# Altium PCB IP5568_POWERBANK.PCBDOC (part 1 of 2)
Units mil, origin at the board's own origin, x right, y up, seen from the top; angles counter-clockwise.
Board outline 4566.93 x 4566.93 mil, 4 copper layers (Top Layer, MID1, MID2, Bottom Layer), stack 38.627 mil thick; 85 components, 61 nets, 294 pads, 184 vias.
Unrouted connection lines stored in the file: 1.
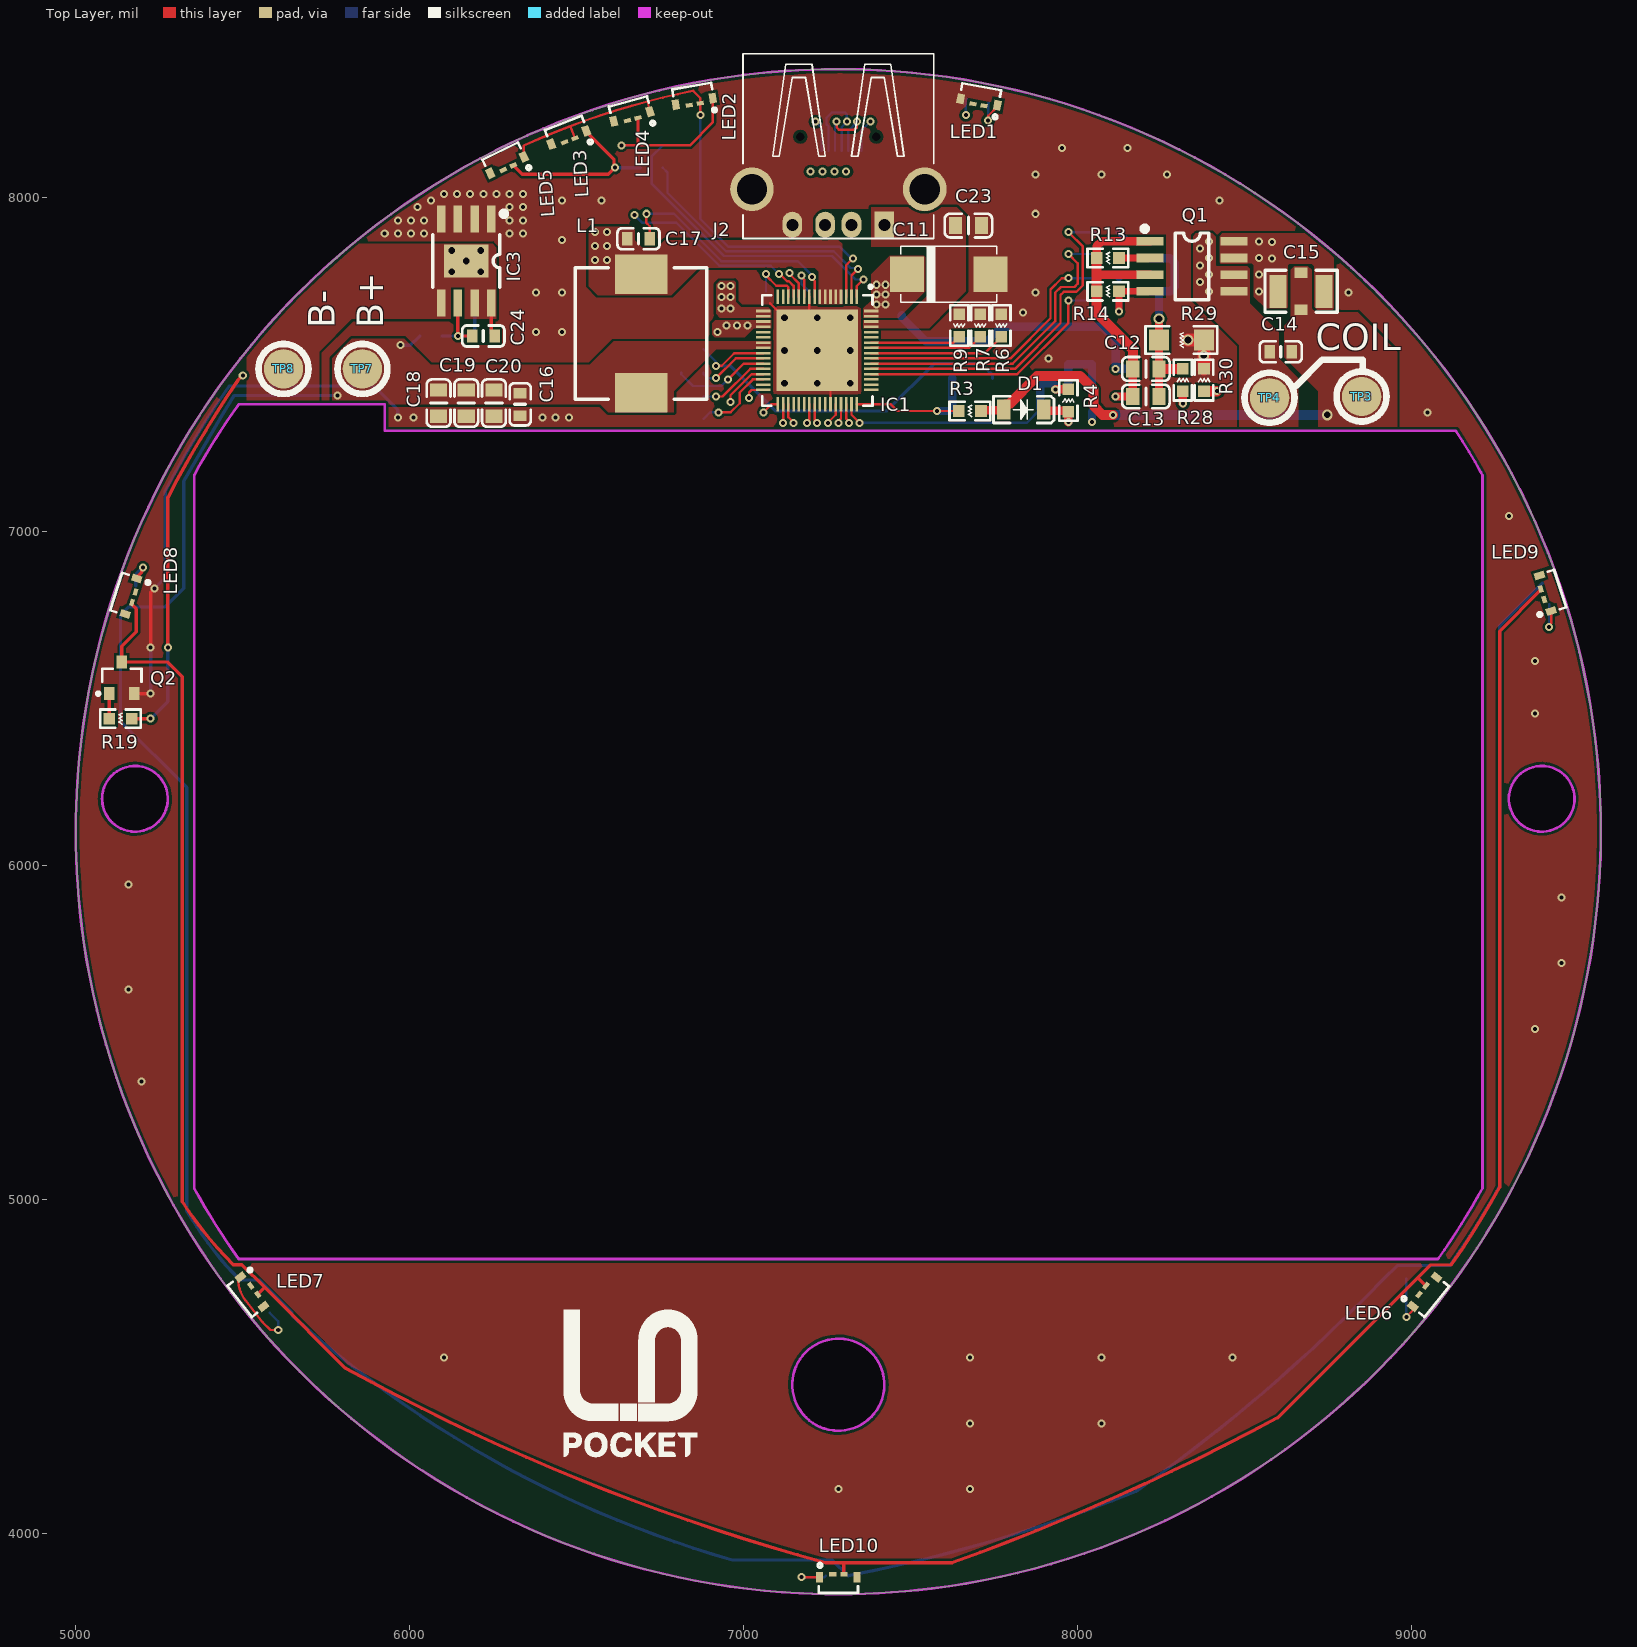
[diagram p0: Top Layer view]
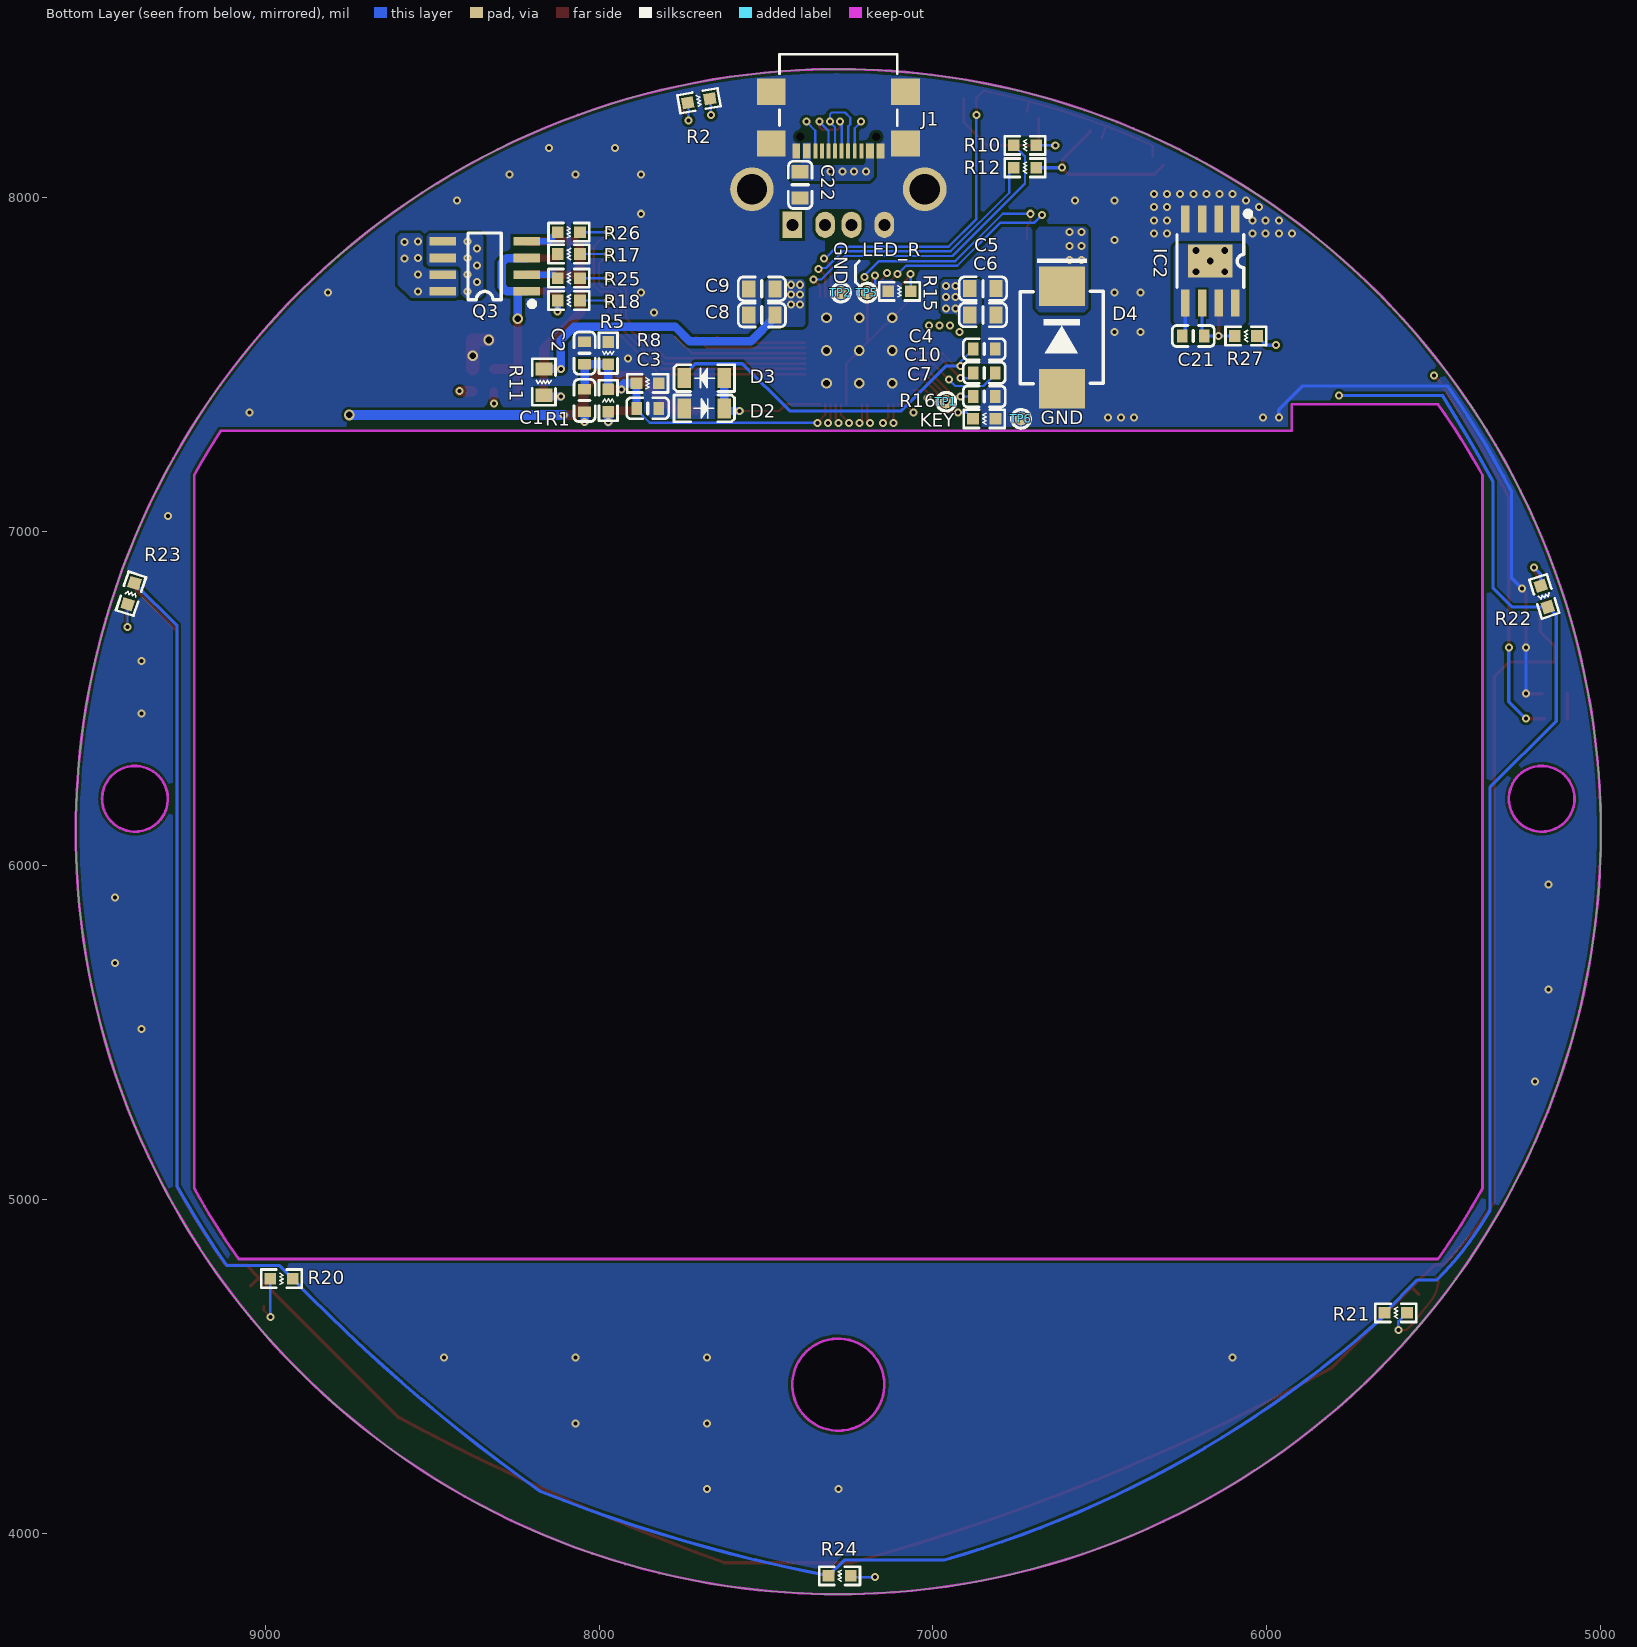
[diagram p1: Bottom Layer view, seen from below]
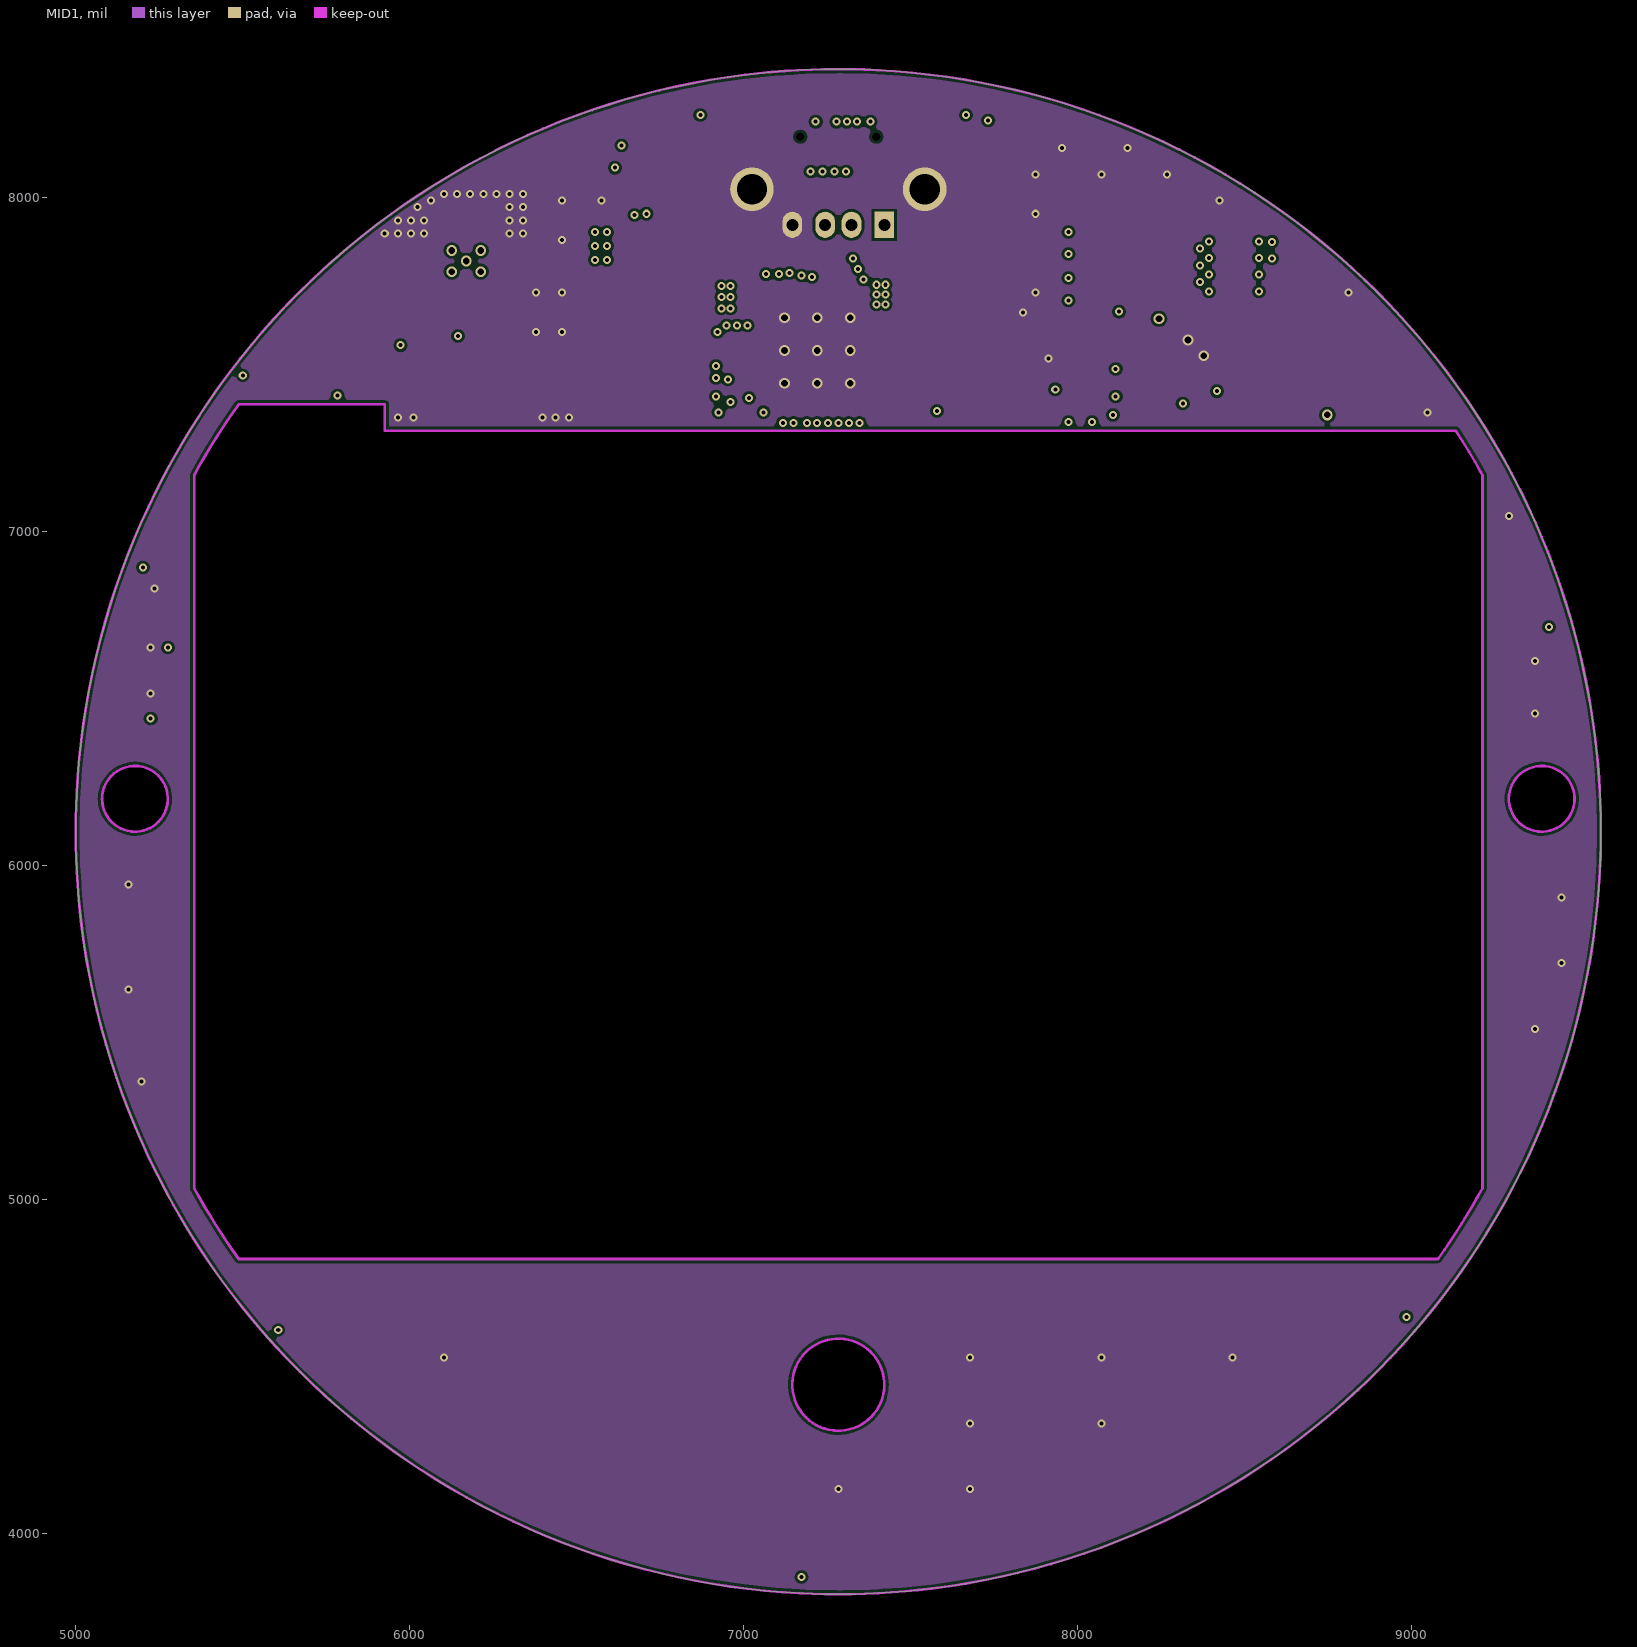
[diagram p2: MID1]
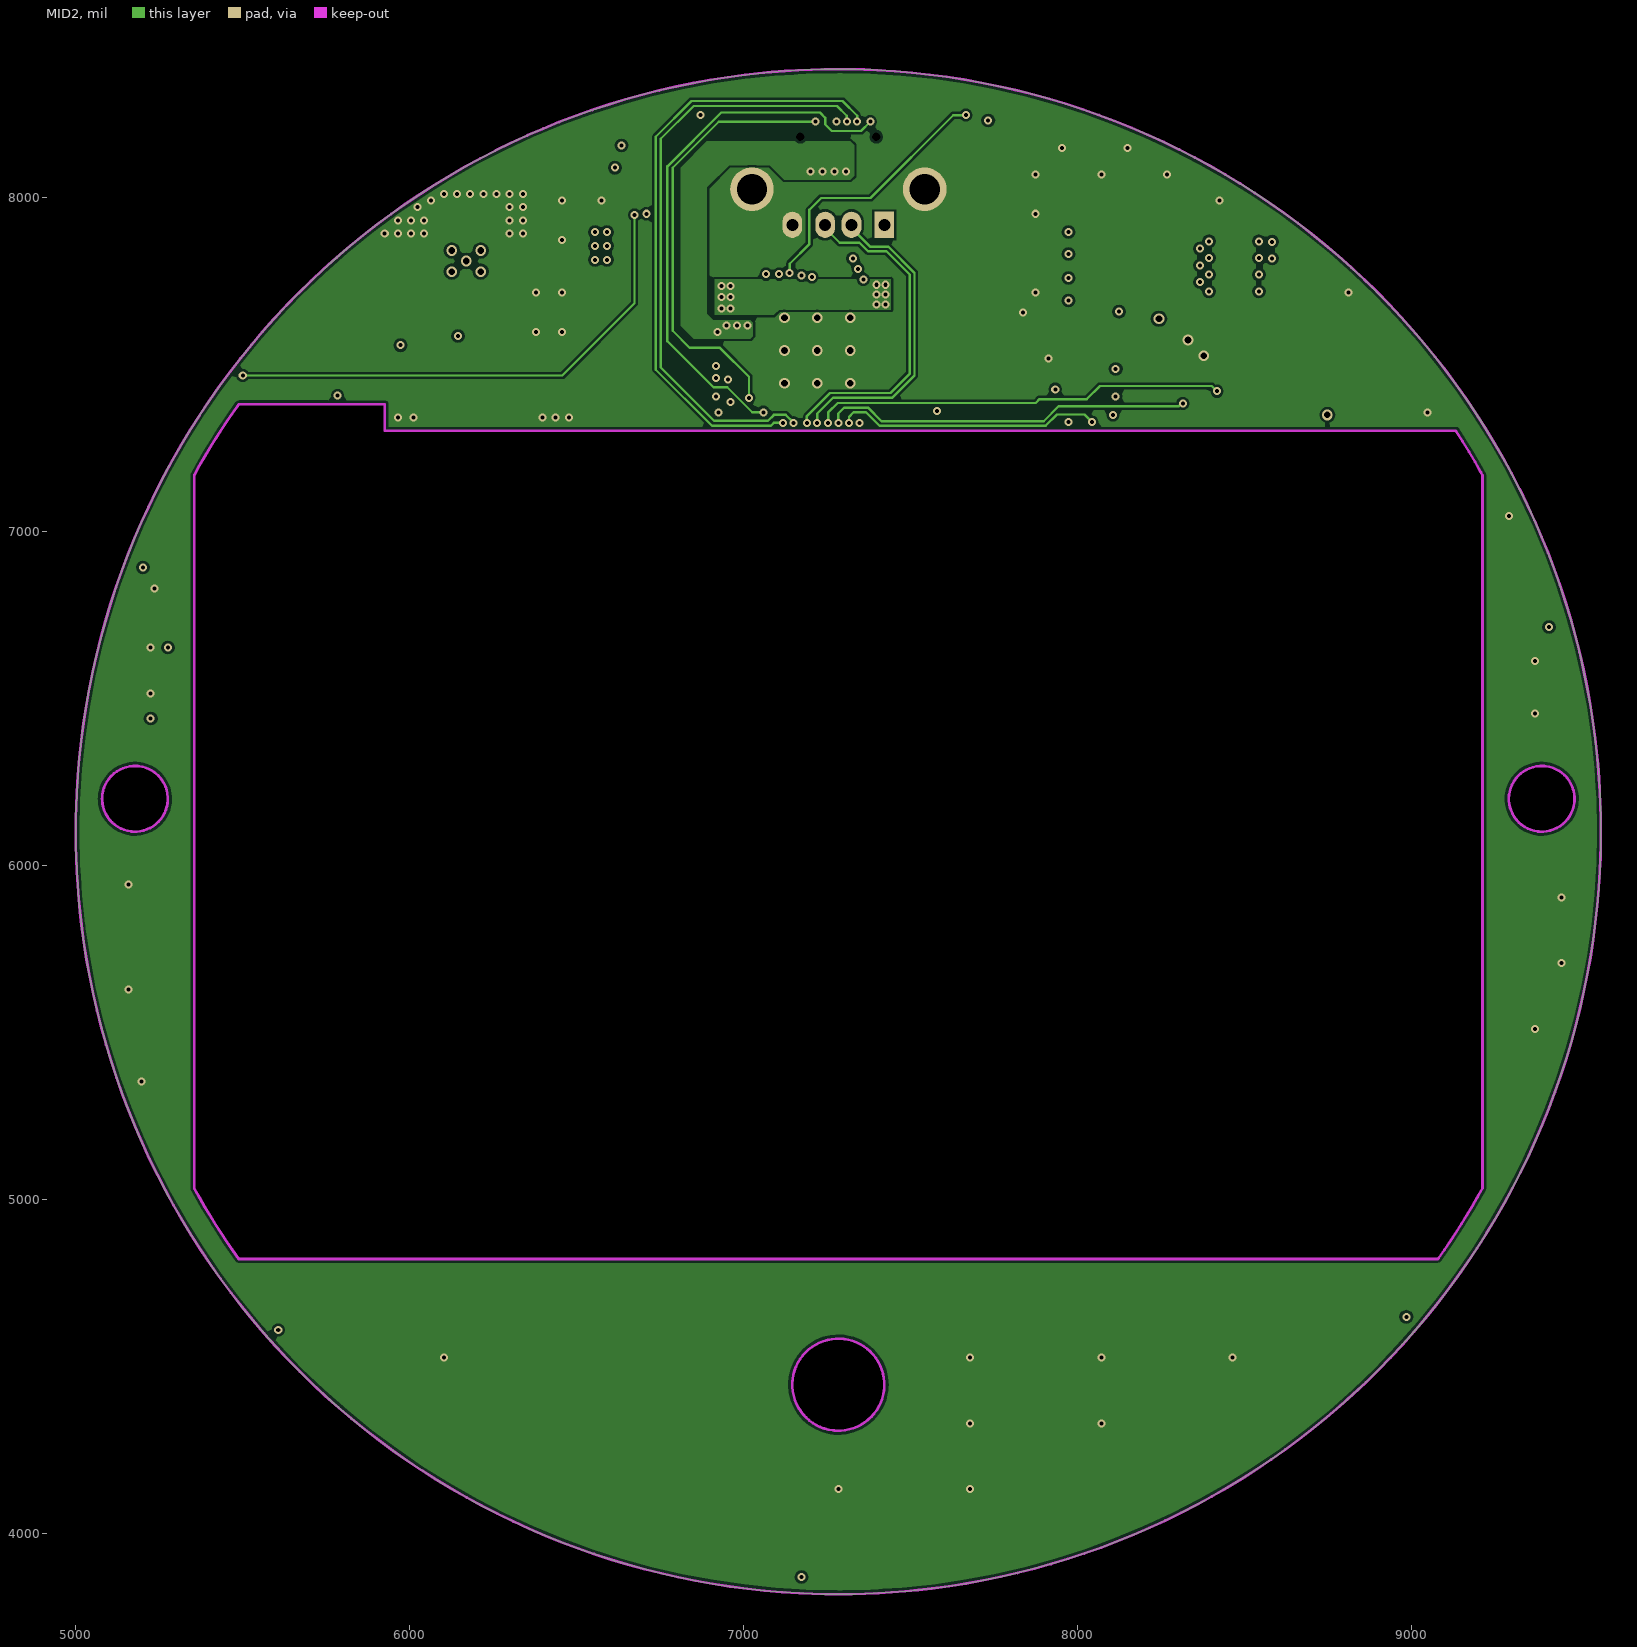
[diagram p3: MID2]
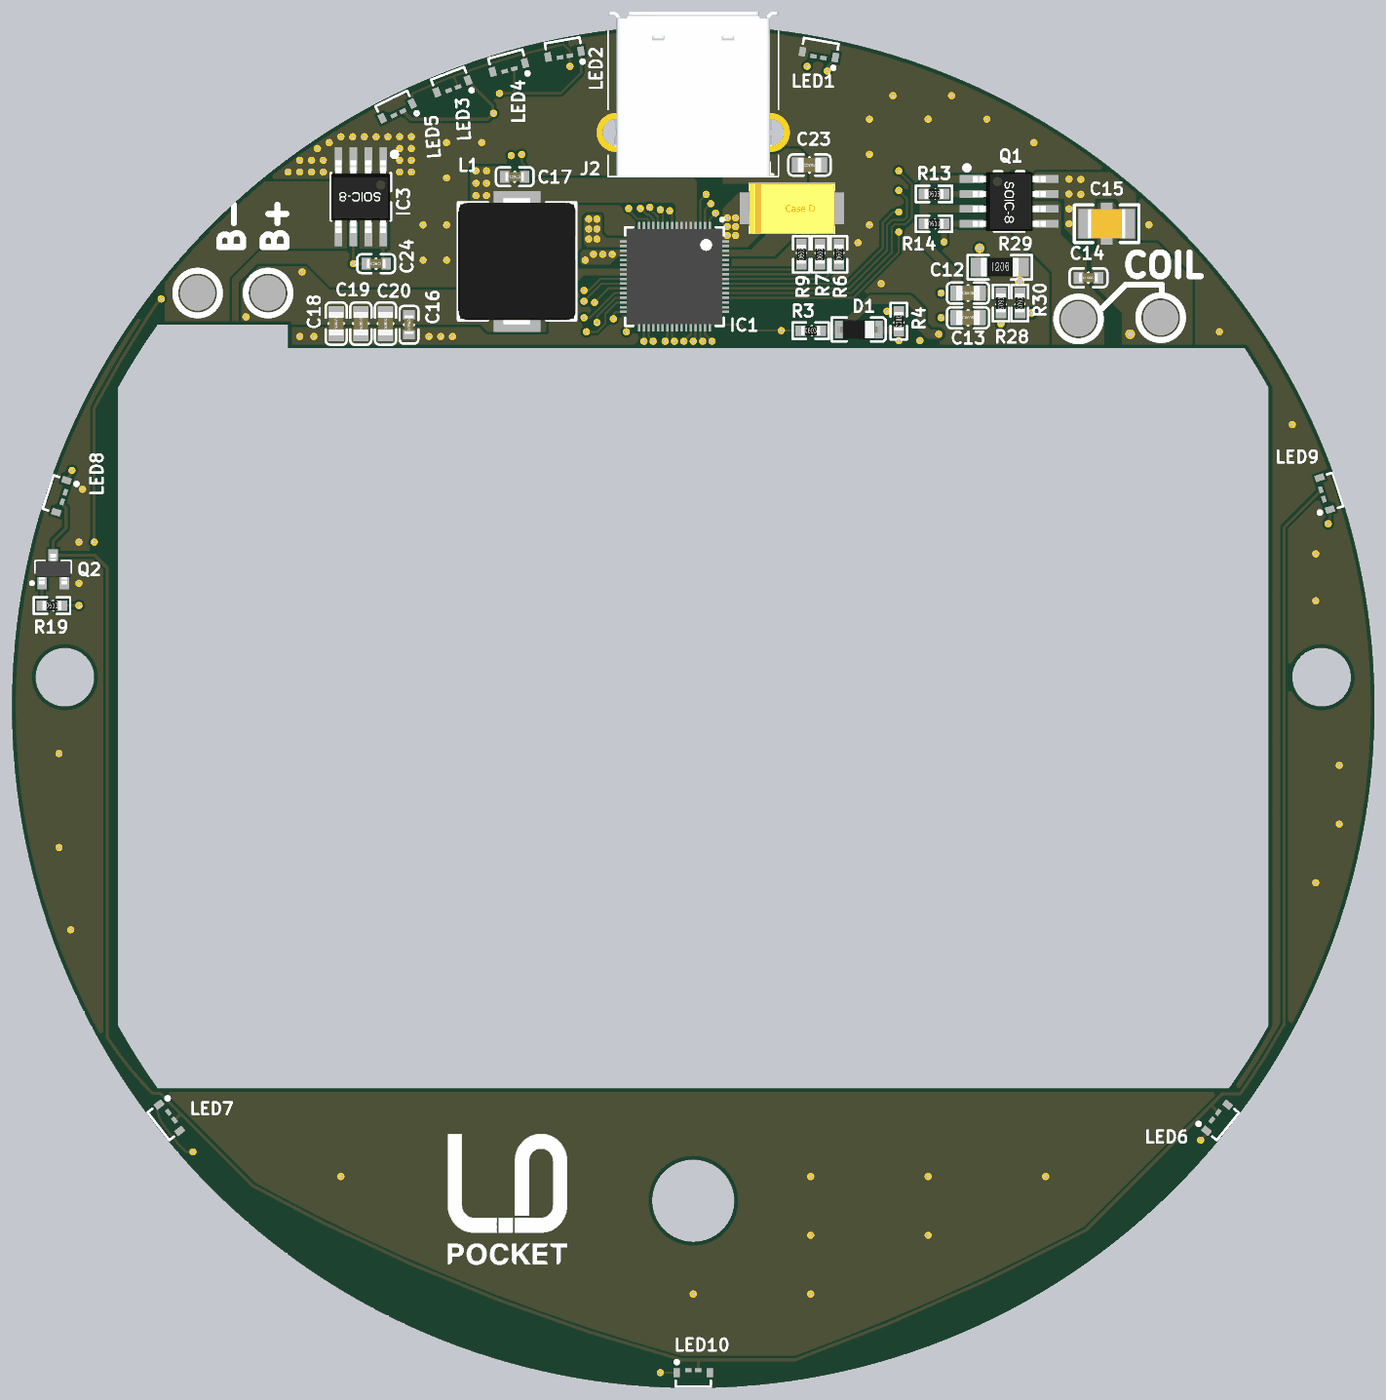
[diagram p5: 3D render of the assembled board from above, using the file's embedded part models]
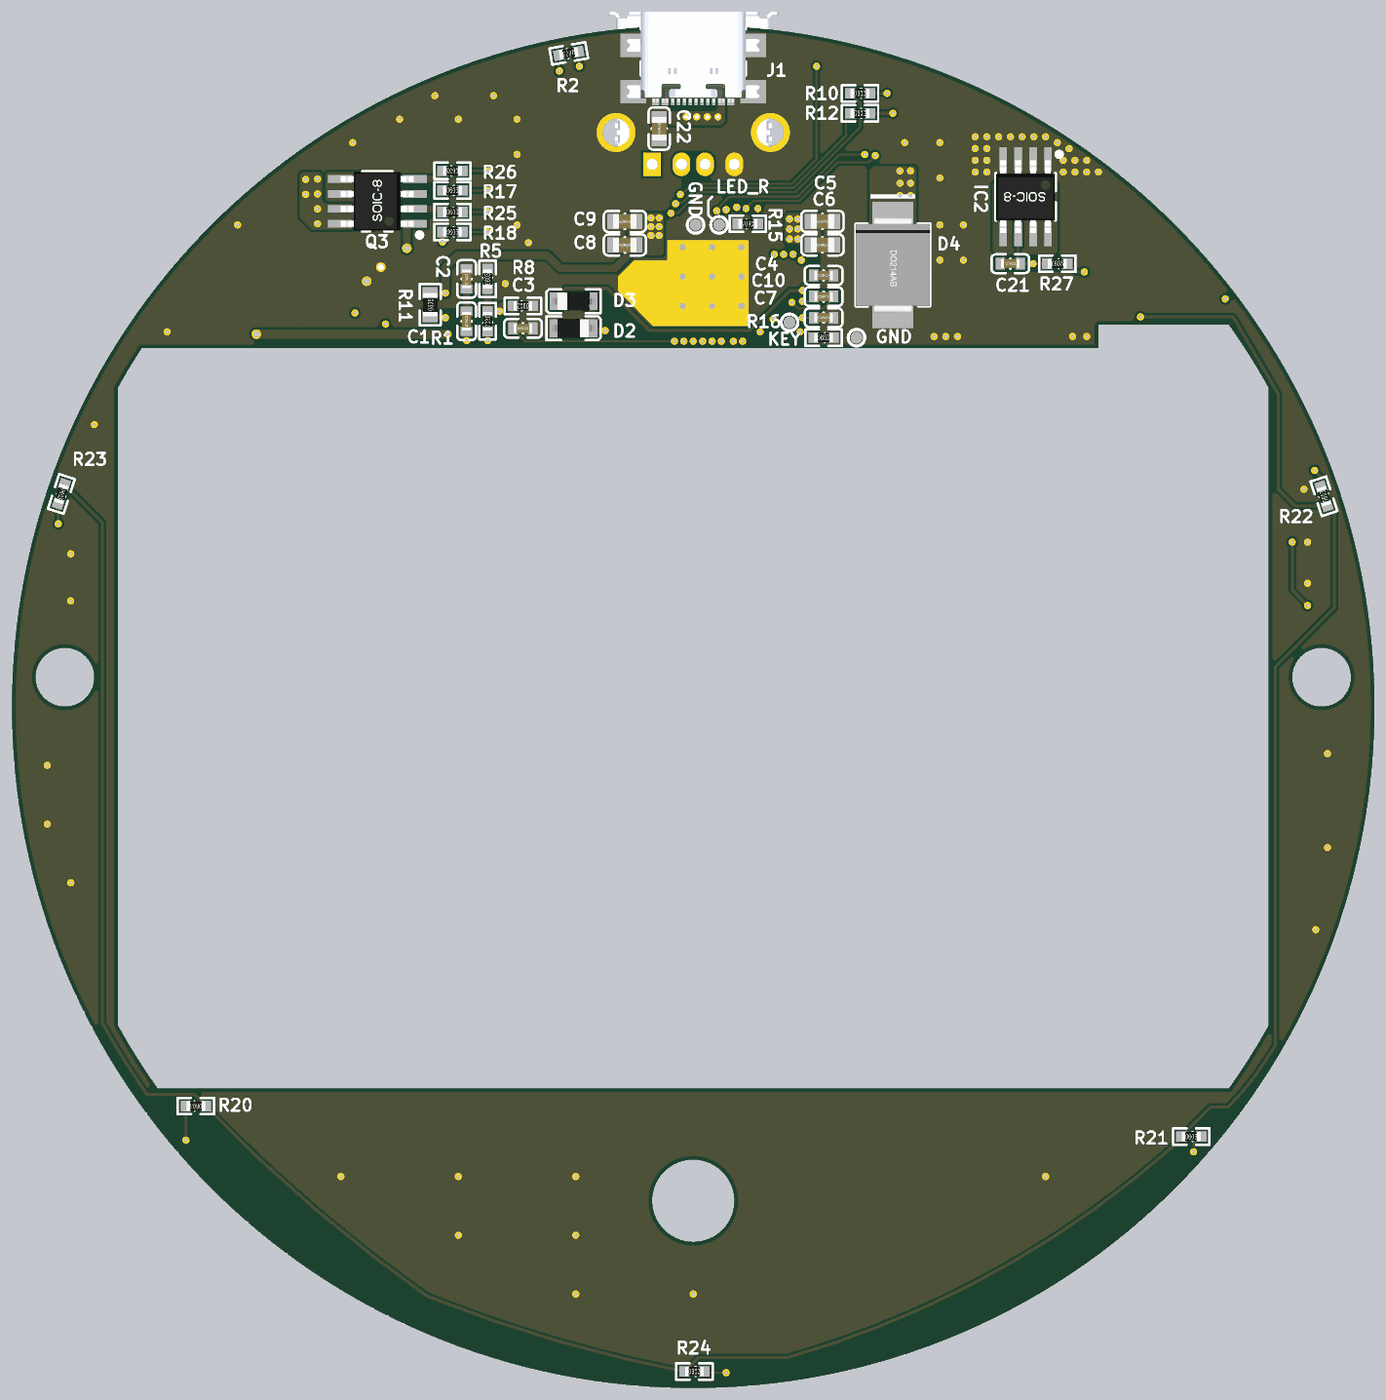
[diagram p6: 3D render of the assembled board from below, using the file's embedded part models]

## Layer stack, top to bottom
Top Solder: solder mask 0.4, Solder Resist, Dk 3.5
Top Layer: signal copper 1.4
Dielectric 1: prepreg 11.0236, PP-006, Dk 4.1
MID1: signal copper 1.378
Dielectric 2: prepreg 11.0236, PP-006, Dk 4.1
MID2: signal copper 1.378
Dielectric1: dielectric 11.0236, FR-4, Dk 4.8
Bottom Layer: signal copper 1.4
Bottom Solder: solder mask 0.4, Solder Resist, Dk 3.5

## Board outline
5000,6102.36 ccw(c7283.46,6102.36) 7283.46,3818.9 ccw(c7283.46,6102.36) 9566.93,6102.36 ccw(c7283.46,6102.36) 7283.46,8385.83 ccw(c7283.46,6102.36)
cut-out: 5418.56,4926.02 cw(c7293.45,6109.41) 5386.41,4978.57 5386.4,4978.57 cw(c7312.75,6120.85) 5355.55,5032.28 5354.33,5034.48 5354.33,7170.25 cw(c7312.02,6084.31) 5386.28,7225.94 cw(c7292.84,6095.68) 5419.37,7279.98 cw(c7274.23,6107.44) 5453.81,7332.77 cw(c7256.69,6119.24) 5487.83,7381.85 5487.91,7381.89 5925.31,7381.89 5925.31,7303.15 9132.65,7303.15 cw(c7294.52,6107.16) 9171.92,7240.51 cw(c7275.49,6095.67) 9207.76,7178.93 9212.6,7170.25 9212.6,5034.48 cw(c7252.63,6121.8) 9181.67,4980.5 cw(c7271.84,6110.43) 9149.55,4927.9 cw(c7290.5,6098.69) 9116.03,4876.28 cw(c7308.61,6086.55) 9080.81,4825.28 9079.07,4822.84 5487.92,4822.84 5487.82,4822.89 cw(c7256.34,6085.25) 5452.27,4874.25 cw(c7274.65,6097.54)
cut-out: 9291.46,6195.76 ccw(c9389.79,6200.8) 9377.72,6103.09 ccw(c9389.7,6201.36) 9384.58,6102.5 ccw(c9389.76,6202.39) 9389.76,6102.36 ccw(c9389.77,6202.41) 9394.79,6102.49 ccw(c9389.75,6200.81) 9487.46,6188.75 ccw(c9389.19,6200.73) 9488.06,6195.6 ccw(c9388.16,6200.78) 9488.19,6200.79 ccw(c9388.15,6200.79) 9488.06,6205.81 ccw(c9389.74,6200.77) 9401.81,6298.48 ccw(c9389.82,6200.22) 9394.95,6299.08 ccw(c9389.77,6199.18) 9389.76,6299.21 ccw(c9389.76,6199.17) 9384.74,6299.09 ccw(c9389.78,6200.76) 9292.07,6212.83 ccw(c9390.33,6200.85) 9291.47,6205.97 ccw(c9391.37,6200.79) 9291.34,6200.79 ccw(c9391.39,6200.78)
cut-out: 7145.85,4439.3 ccw(c7283.5,4446.35) 7266.61,4309.56 ccw(c7283.39,4447.14) 7276.21,4308.73 ccw(c7283.46,4448.59) 7283.47,4308.54 ccw(c7283.48,4448.6) 7290.51,4308.72 ccw(c7283.45,4446.36) 7420.24,4429.47 ccw(c7282.67,4446.25) 7421.08,4439.07 ccw(c7281.22,4446.33) 7421.27,4446.33 ccw(c7281.2,4446.34) 7421.09,4453.37 ccw(c7283.44,4446.32) 7300.33,4583.11 ccw(c7283.56,4445.54) 7290.73,4583.94 ccw(c7283.48,4444.09) 7283.47,4584.13 ccw(c7283.47,4444.06) 7276.44,4583.95 ccw(c7283.49,4446.3) 7146.7,4463.19 ccw(c7284.27,4446.42) 7145.86,4453.59 ccw(c7285.72,4446.34) 7145.67,4446.33 ccw(c7285.74,4446.33)
cut-out: 5165.12,6103.09 cw(c5177.19,6200.8) 5078.86,6195.76 cw(c5178.79,6200.78) 5078.74,6200.79 cw(c5178.77,6200.79) 5078.87,6205.97 cw(c5177.73,6200.85) 5079.47,6212.83 cw(c5177.18,6200.76) 5172.14,6299.09 cw(c5177.16,6199.17) 5177.16,6299.21 cw(c5177.17,6199.18) 5182.35,6299.08 cw(c5177.22,6200.22) 5189.21,6298.48 cw(c5177.14,6200.77) 5275.46,6205.81 cw(c5175.55,6200.79) 5275.59,6200.79 cw(c5175.56,6200.78) 5275.46,6195.6 cw(c5176.59,6200.73) 5274.86,6188.75 cw(c5177.15,6200.81) 5182.19,6102.49 cw(c5177.17,6202.41) 5177.16,6102.36 cw(c5177.16,6202.39) 5171.98,6102.5 cw(c5177.1,6201.36)

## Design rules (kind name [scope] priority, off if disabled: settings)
AcuteAngle [All] p1: minimum=6.00000000000000E+0001 checktracksonly=FALSE
BoardOutlineClearance [All] p1: gap=10 ignorepadtopadclearanceinfootprint=FALSE
Clearance [All] p1: gap=7 ignorepadtopadclearanceinfootprint=FALSE except(8: Arc-Poly Track-Poly SMDPad-Poly THPad-Poly Via-Poly Fill-Poly Poly-Poly Poly-Region Poly-Text Poly-Hole)
FabricationTestPointUsage TestPointUsage [All] p1: valid=0 allowmultiple=FALSE
FabricationTestpoint Testpoint [All] p1: side=3 testpointundercomponent=TRUE minsize=40 maxsize=100 preferedsize=60 minholesize=0 maxholesize=40 preferedholesize=32 testpointgrid=1 allowsidetop=TRUE allowsidebottom=TRUE usegrid=TRUE gridtolerance=0.01
HoleSize [All] p1: absolutevalues=TRUE maxlimit=100 minlimit=12 maxpercent=80.000 minpercent=20.000
HoleToHoleClearance [All] p1: gap=22 allowstackedmicrovias=TRUE
MinimumAnnularRing [All] p1: minimumring=6
PolygonConnect [All] p1: connectstyle=Direct reliefconductorwidth=20 reliefentries=4 polygonreliefangle="90 Angle" airgapwidth=10
RoutingLayers [All] p1: top layer_v5=TRUE mid layer 1_v5=FALSE mid layer 2_v5=FALSE bottom layer_v5=TRUE
RoutingVias [All] p1: holewidth=12 width=24 viastyle="Through Hole" minholewidth=12 minwidth=24 maxholewidth=24 maxwidth=40
SilkToSilkClearance [All] p1: silktosilkclearance=8
SilkToSolderMaskClearance SilkscreenOverComponentPads [IsPad] p1: minsilkscreentomaskgap=8 clearancetoexposedcopper=TRUE
SolderMaskExpansion [All] p1: expansion=0 istentingtop=FALSE
Width [All] p1: maxlimit=100 minlimit=7 preferedwidth=10
23 further rules are at their usual default settings.

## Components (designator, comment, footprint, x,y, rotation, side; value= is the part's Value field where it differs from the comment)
C1 "15nF" C0603 8043.31,7393.7 r270 bottom
C2 "15nF" C0603 8043.31,7535.43 r90 bottom
C3 "2.2nF" C0603 7854.33,7370.08 r180 bottom
C4 "2.2uF/16V" C0603 6846.46,7547.24 r0 bottom
C5 "22uF/25V" C0805 6850.39,7728.35 r180 bottom
C6 "22uF/25V" C0805 6850.39,7649.61 r180 bottom
C7 "2.2uF/16V" C0603 6846.46,7405.51 r0 bottom
C8 "22uF/25V" C0805 7512.49,7649.3 r0 bottom
C9 "22uF/25V" C0805 7512.49,7728.04 r0 bottom
C10 "100nF/25V" C0603 6846.46,7476.38 r180 bottom
C11 "100F/25V" CAP_TAND_7343 7614.17,7771.65 r0 top
C12 "10uF/25V" C0805 8204.72,7488.19 r0 top
C13 "10uF/25V" C0805 8204.72,7405.51 r0 top
C14 "NC/2nF" C0603 8608.27,7539.37 r180 top
C15 "400nF/100V" C1410 8669.29,7720.47 r180 top
C16 "100nF/16V" C0603 6330.71,7381.89 r270 top
C17 "100nF/25V" C0603 6685.04,7877.95 r180 top
C18 "22uF/16V" C0805 6086.61,7385.83 r270 top
C19 "22uF/16V" C0805 6169.29,7385.83 r270 top
C20 "22uF/16V" C0805 6251.97,7385.83 r270 top
C21 "100nF/16V" C0603 6220.47,7586.61 r0 bottom
C22 "10uF/25V" C0805 7397.64,8039.37 r270 bottom
C23 "10uF/25V" C0805 7673.23,7917.32 r0 top
C24 "100nF/16V" C0603 6220.47,7586.61 r0 top
D1 "1N5819" SOD-123 7838.58,7366.14 r270 top
D2 "1N5819" SOD-123 7685.04,7370.08 r270 bottom
D3 "1N5819" SOD-123 7685.04,7460.63 r90 bottom
D4 "SS34" "DIODE_ DO-214AB(SMC)" 6614.17,7582.43 r270 bottom
IC1 "IP5568" QFN64 7220.47,7543.31 r270 top
IC2 "XB8089D" SOP-08 6169.29,7811.02 r270 bottom
IC3 "XB8089D" SOP-08 6169.29,7811.02 r270 top
J1 "USB-C" USB-C_USB4110-GF-A 7283.46,8183.11 r0 bottom
J2 "USB-A" USB_A_F 7283.46,8026.28 r180 top
L1 "2.2uH" INDUCTOR_10X10X4 6692.91,7594.49 r270 top
LED1 "RGB" LED_RGB 7704.72,8287.4 r350 top
LED2 "RGB" LED_RGB 6852.1,8289.09 r10 top
LED3 "RGB" LED_RGB 6476.38,8181.1 r21 top
LED4 "RGB" LED_RGB 6665.35,8244.09 r15 top
LED5 "RGB" LED_RGB 6291.34,8098.43 r26 top
LED6 "RGB" LED_RGB 9039.37,4724.32 r231 top
LED7 "RGB" LED_RGB 5527.56,4724.41 r128 top
LED8 "RGB" LED_RGB 5165.35,6807.09 r72 top
LED9 "RGB" LED_RGB 9400.58,6815.98 r288 top
LED10 "RGB" LED_RGB 7283.46,3870.08 r180 top
Q1 "RU30S15H" SO-08 8342.52,7795.28 r0 top
Q2 "BSS138" SOT23-3 5137.8,6562.99 r0 top
Q3 "RUH30D20H" SO-08 8342.52,7795.28 r0 bottom
R1 "3.3K" R0603 7972.44,7393.7 r270 bottom
R2 "100R" R0603 7700.79,8291.34 r350 bottom
R3 "20K" R0603 7677.17,7362.2 r0 top
R4 "100K" R0603 7972.44,7393.7 r270 top
R5 "33K" R0603 7972.44,7535.43 r90 bottom
R6 "50K" R0603 7771.65,7618.11 r90 top
R7 "115K" R0603 7708.66,7618.11 r90 top
R8 "10K" R0603 7854.33,7444.88 r0 bottom
R9 "20K" R0603 7645.67,7618.11 r90 top
R10 "100R" R0603 6724.41,8157.48 r180 bottom
R11 "0R" R0805 8165.35,7448.82 r90 bottom
R12 "100R" R0603 6724.41,8090.55 r180 bottom
R13 "NC/10K" R0603 8090.55,7820.28 r0 top
R14 "NC/10K" R0603 8090.55,7720.28 r0 top
R15 "51K" R0603 7100.39,7720.47 r0 bottom
R16 "51K" R0603 6846.46,7338.58 r180 bottom
R17 "2R" R0603 8090.55,7832.09 r180 bottom
R18 "2R" R0603 8090.55,7692.91 r180 bottom
R19 "100R" R0603 5133.86,6440.94 r0 top
R20 "1K" R0603 8950.79,4763.78 r0 bottom
R21 "1K" R0603 5614.17,4661.42 r180 bottom
R22 "1K" R0603 5169.29,6807.09 r72 bottom
R23 "1K" R0603 9401.57,6814.96 r288 bottom
R24 "1K" R0603 7279.53,3874.02 r180 bottom
R25 "2R" R0603 8090.55,7759.84 r180 bottom
R26 "2R" R0603 8090.55,7897.64 r0 bottom
R27 "1K" R0603 6062.99,7586.61 r180 bottom
R28 "0R" R0603 8314.96,7454.72 r270 top
R29 "20mR" R1206 8311.02,7574.8 r0 top
R30 "0R" R0603 8378.52,7454.72 r270 top
TP1 "TP" TESTPOINT_1MM_ROUND 6960.63,7389.76 r180 bottom
TP2 "TP" TESTPOINT_1MM_ROUND 7275.59,7716.54 r90 bottom
TP3 "COIL1" TEST_POINT_3MM_ROUND 8850.39,7405.51 r180 top
TP4 "COIL2" TEST_POINT_3MM_ROUND 8574.8,7401.57 r180 top
TP5 "TP" TESTPOINT_1MM_ROUND 7196.85,7716.54 r90 bottom
TP6 "TP" TESTPOINT_1MM_ROUND 6736.22,7338.58 r180 bottom
TP7 "BAT+" TEST_POINT_3MM_ROUND 5858.27,7488.19 r180 top
TP8 "BAT-" TEST_POINT_3MM_ROUND 5622.05,7488.19 r180 top

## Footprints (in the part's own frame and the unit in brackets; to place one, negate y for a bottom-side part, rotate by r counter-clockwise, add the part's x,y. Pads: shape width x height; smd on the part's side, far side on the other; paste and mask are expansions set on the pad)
C0603 [mm] "Chip Capacitor, 2-Leads, Body 1.60x0.80mm, IPC Medium Density"
  rect 0.8x1 smd: 1(-0.85,0) 2(0.85,0)
  silkscreen extent -1.6,-0.8 1.6,0.8, body extent -0.8,-0.4 0.8,0.4, height 0.8
C0805 [mm] "Chip Capacitor, 2-Leads, Body 2.00x1.25mm, IPC Medium Density"
  rect 1x1.3 smd: 1(-1,0) 2(1,0)
  silkscreen extent -1.8,-0.9 1.8,0.9, body extent -1.01,-0.63 1,0.62, height 0.94
C1410 [mm]
  rect 1.3x2.5 smd: A(-1.75,0) B(1.75,0)
  rect 1x0.8 smd: G1(0,1.4) G2(0,-1.4)
  silkscreen extent -2.75,-1.6 2.75,1.6, body extent -1.6,-1.25 1.6,1.25, height 1.4
CAP_TAND_7343 [mil] "7343 Metric, 7.30mm x 4.30mm"
  rect 101x107 smd: 1(-125,0) 2(125,0)
  silkscreen extent -144,-84 144,84, body extent -144,-85 144,85, height 110
"DIODE_ DO-214AB(SMC)" [mm]
  rect 3x3.5 smd: A(3.888,0) K(-3.888,0)
  silkscreen extent -6,-3.15 3.51,3.15, body extent -4.06,-3.15 4.06,3.15, height 2.67
INDUCTOR_10X10X4 [mm]
  rect 3x4 smd: 1(-4.5,0) 2(4.5,0)
  silkscreen extent -5,-5 5,5, body extent -5.38,-5 5.38,5, height 3.97
LED_RGB [mm]
  rect 0.55x0.78 smd: 1(1.425,0) 4(-1.425,0)
  rect 0.55x0.34 smd: 2(0.425,-0.22) 3(-0.425,-0.22)
  silkscreen extent -1.5,-1.05 1.55,1.18, body extent -1.5,-0.2 1.5,1.18, height 1
QFN64 [mm] "QFN, 64-Leads, Body 8.00x8.00mm, Pitch 0.40mm, Thermal Pad 6.20x6.20mm, IPC Low Density"
  rect 1.1x0.2 smd: 1(-4.1,3) 2(-4.1,2.6) 3(-4.1,2.2) 4(-4.1,1.8) 5(-4.1,1.4) 6(-4.1,1) 7(-4.1,0.6) 8(-4.1,0.2) 9(-4.1,-0.2) 10(-4.1,-0.6) 11(-4.1,-1) 12(-4.1,-1.4) 13(-4.1,-1.8) 14(-4.1,-2.2) 15(-4.1,-2.6) 16(-4.1,-3) 33(4.1,-3) 34(4.1,-2.6) 35(4.1,-2.2) 36(4.1,-1.8) 37(4.1,-1.4) 38(4.1,-1) 39(4.1,-0.6) 40(4.1,-0.2) 41(4.1,0.2) 42(4.1,0.6) 43(4.1,1) 44(4.1,1.4) 45(4.1,1.8) 46(4.1,2.2) 47(4.1,2.6) 48(4.1,3)
  rect 0.2x1.1 smd: 17(-3,-4.1) 18(-2.6,-4.1) 19(-2.2,-4.1) 20(-1.8,-4.1) 21(-1.4,-4.1) 22(-1,-4.1) 23(-0.6,-4.1) 24(-0.2,-4.1) 25(0.2,-4.1) 26(0.6,-4.1) 27(1,-4.1) 28(1.4,-4.1) 29(1.8,-4.1) 30(2.2,-4.1) 31(2.6,-4.1) 32(3,-4.1) 49(3,4.1) 50(2.6,4.1) 51(2.2,4.1) 52(1.8,4.1) 53(1.4,4.1) 54(1,4.1) 55(0.6,4.1) 56(0.2,4.1) 57(-0.2,4.1) 58(-0.6,4.1) 59(-1,4.1) 60(-1.4,4.1) 61(-1.8,4.1) 62(-2.2,4.1) 63(-2.6,4.1) 64(-3,4.1)
  rect 6.2x6.2 smd: 65(0,0)
  silkscreen extent -4.97,-4.2 4.2,4.2, body extent -4.06,-4.06 4.06,4.06, height 0.8
R0603 [mil] "Chip Resistor, 2-Leads, Body 1.55x0.85mm, IPC Medium Density"
  rect 35x35 smd: 1(-33.46,0) 2(33.46,0)
  silkscreen extent -61,-28 61,28, body extent -31,-16 32,16, height 16
R0805 [mm] "Chip Capacitor, 2-Leads, Body 2.00x1.25mm, IPC Medium Density"
  rect 1x1.3 smd: 1(-1,0) 2(1,0)
  silkscreen extent -1.76,-0.89 1.76,0.89, body extent -1,-0.63 1,0.62, height 0.5
R1206 [mm]
  rect 1.5x1.6 smd: 1(-1.714,0) 2(1.714,0)
  silkscreen extent -2.73,-1.04 2.73,1.04, body extent -1.6,-0.8 1.6,0.8, height 0.56
SO-08 [mil]
  rect 80x25.59 smd: 1(-125.75,75) 2(-125.75,25) 3(-125.75,-25) 4(-125.75,-75) 5(125.75,-75) 6(125.75,-25) 7(125.75,25) 8(125.75,75)
  silkscreen extent -150,-100 50,120, body extent -122,-99 122,98, height 75
SOD-123 [mil]
  rect 60x40 smd: A(0,-60) K(0,60)
  silkscreen extent -40,-91 40,91, body extent -31,-73 31,73, height 50
SOP-08 [mm]
  rect 2.032x0.65 smd: 1(-3.194,1.905) 2(-3.194,0.635) 3(-3.194,-0.635) 4(-3.194,-1.905) 5(3.194,-1.905) 6(3.194,-0.635) 7(3.194,0.635) 8(3.194,1.905)
  rect 2.5x3.4 smd: 9(0,0)
  silkscreen extent -3.8,-2.54 2,3.06, body extent -3.09,-2.51 3.11,2.49, height 1.9
SOT23-3 [mm] "SOT23, 3-Leads, Body 2.90x2.45mm, Pitch 0.95mm, IPC Medium Density"
  rect 0.8x1 smd: 1(-0.95,-1.2) 2(0.95,-1.2) 3(0,1.2)
  silkscreen extent -1.92,-1.32 1.5,0.7, body extent -1.5,-1.3 1.5,1.3, height 1.1
TEST_POINT_3MM_ROUND [mm]
  round 3 smd: 1(0,0)
  silkscreen extent -1.9,-1.9 1.9,1.9
TESTPOINT_1MM_ROUND [mm]
  round 1 smd: 1(0,0)
  silkscreen extent -0.71,-0.71 0.7,0.71
USB-C_USB4110-GF-A [mm]
  rect 0.6x1.15 smd: A1/B12(-3.2,1.075) A4/B9(-2.4,1.075) B1/A12(3.2,1.075) B4/A9(2.4,1.075)
  rect 0.3x1.15 smd: A5(-1.25,1.075) A6(-0.25,1.075) A7(0.25,1.075) A8(1.25,1.075) B5(1.75,1.075) B6(0.75,1.075) B7(-0.75,1.075) B8(-1.75,1.075)
  rect 2.18x2 smd: S1(-5.11,0.5) S2(5.11,0.5) S3(-5.11,-3.43) S4(5.11,-3.43)
  round 0 hole 0.65 unplated: ""(-2.89,0) ""(2.89,0)
  silkscreen extent -4.47,-6.28 4.47,-0.86, body extent -5.65,-6.28 5.65,1.4, height 3.26
USB_A_F [mm]
  rect 1.5x2 hole 0.92: 1(-3.5,2.71)
  oval 1.5x2 hole 0.92: 2(-1,2.71) 3(1,2.71) 4(3.5,2.71)
  round 3.316 hole 2.3: P1(-6.57,0) P2(6.57,0)
  silkscreen extent -7.25,-10.3 7.25,3.75, body extent -7.25,-10.3 7.25,3.7, height 7.8

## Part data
C1 C2: library part CAPACITOR, "Capacitor, 0603, 15nF, 10%, 50V"
C3: library part CAPACITOR, "Capacitor, 0603, 2.2nF, 10%, 50V"
C4 C7: library part CAPACITOR, "Capacitor, 0603, 2.2uF, 10%, 16V"
C5 C6 C8 C9: library part CAPACITOR, "Capacitor, 0805, 22uF, 10%, 25V"
C10 C17: library part CAPACITOR, "Capacitor, 0603, 100nF, 10%, 25V"
C11: library part CAP_TAN_100uF_25V, "KEMET Tantalum Capacitor  100µF/25V Case-D (7343 Metric) 300mOhm", Capacitance=100uF, Case Code (Imperial)=2917, Case Code (Metric)=7343, Dielectric Material=Tantalum, ESR (Equivalent Series Resistance)=300mR, Leakage Current=25uA, Manufacturer=KEMET, Manufacturer Part Number=T491X107K025AT, Max Operating Temperature=125°C, Min Operating Temperature=-55°C, Package Quantity=1, Ripple Current=742mA, Supplier Part Number 1=399-8410-1-ND, Tolerance=10%, Voltage=25V
C12 C13 C22 C23: library part CAPACITOR, "Capacitor, 0805, 10uF, 10%, 25V"
C14: library part CAPACITOR, "Capacitor, 0603, NC/2nF, 10%, 50V"
C15: library part C1410_400nF_100V, "400nF ±20% 100V Ceramic Capacitor X7R 1410 (3524 Metric)", Capacitance=400nF, Case Code (Imperial)=1410, Case Code (Metric)=3527, Dielectric=X7R, Manufacturer=Johanson, Manufacturer Part Number=101X44W404MV4E, Max Operating Temperature=125°C, Min Operating Temperature=-55°C, Package Quantity=2000, Supplier Part Number 1=709-1245-1-ND, Tolerance=20%, Voltage Rating=100V
C16 C21 C24: library part CAPACITOR, "Capacitor, 0603, 100nF, 10%, 16V"
C18 C19 C20: library part CAPACITOR, "Capacitor, 0805, 22uF, 10%, 16V"
D1 D2 D3: library part DIODE_1N5819, "Diode Schottky 40V 1A Surface Mount SOD-123", Average Rectified Current=1A, Capacitance=110pF, Case/Package=SOD-123-2, Forward Voltage=450mV, Manufacturer=Diodes, Manufacturer Part Number=1N5819HW-7-F, Max Forward Surge Current (Ifsm)=25A, Max Operating Temperature=125°C, Max Power Dissipation=450mW, Max Repetitive Reverse Voltage (Vrrm)=40V, Min Operating Temperature=-65°C, Package Quantity=3000, Peak Reverse Current=50uA, Supplier Part Number 1=1N5819HW-FDICT-ND
D4: library part DIODE_SS34, "Diode Schottky 40V 3A Surface Mount SMC (DO-214AB)"
IC1: library part IP5568_SOC, "Bi-directional PD3.0 and Fast Charge protocol Power Bank & Wireless Charger SOC"
IC2 IC3: "XB8089D One Cell Lithium-ion/Polymer Battery Protection IC"
J1: "USB-C (USB TYPE-C) USB 2.0 Receptacle Connector 24 (16+8 Dummy) Position Surface Mount, Right Angle; Through Hole", Manufacturer="Global Connector Technology", Manufacturer Part Number=USB4110-GF-A, Supplier Part Number 1=1117943
J2: library part USB_A_F, "USB-A (USB TYPE-A) USB 2.0 Receptacle Connector 4 Position Through Hole, Right Angle", Color=White, Flammability Rating="UL94 V-0", Manufacturer="Amphenol FCI", Manufacturer Part Number=87520-0010BLF, Max Operating Temperature=85°C, Min Operating Temperature=-40°C, Package Quantity=42, Supplier Part Number 1=609-1045-ND
L1: library part INDUCTOR_2.2UH, "2.2uH ±20% SMD,10x10x4mm Inductors (SMD) RoHS"
LED1: library part LEDR_RGB, "Red, Green, Blue (RGB) 624nm Red, 525nm Green, 470nm Blue LED Indicator - Discrete 2V Red, 3.3V Green, 3.3V Blue 4-SMD", Case/Package=SMD/SMT, Color=Blue,Green,Red, Forward Voltage=3.3V, Lens Color=Colorless, Manufacturer=Everlight, Manufacturer Part Number=EASV3015RGBA0, Supplier Part Number 1=9074476, Test Current=20mA
LED2 LED3 LED4 LED5: library part LEDB_RGB, "Red, Green, Blue (RGB) 624nm Red, 525nm Green, 470nm Blue LED Indicator - Discrete 2V Red, 3.3V Green, 3.3V Blue 4-SMD", Case/Package=SMD/SMT, Color=Blue,Green,Red, Forward Voltage=3.3V, Lens Color=Colorless, Manufacturer=Everlight, Manufacturer Part Number=EASV3015RGBA0, Supplier Part Number 1=9074476, Test Current=20mA
LED6 LED7 LED8 LED9 LED10: library part LEDG_RGB, "Red, Green, Blue (RGB) 624nm Red, 525nm Green, 470nm Blue LED Indicator - Discrete 2V Red, 3.3V Green, 3.3V Blue 4-SMD", Case/Package=SMD/SMT, Color=Blue,Green,Red, Forward Voltage=3.3V, Lens Color=Colorless, Manufacturer=Everlight, Manufacturer Part Number=EASV3015RGBA0, Supplier Part Number 1=9074476, Test Current=20mA
Q1: "P-Channel Advanced Power MOSFET -30V/-15A"
Q2: library part BSS138-7-F, "N-Channel 50V 200mA (Ta) 300mW (Ta) Surface Mount SOT-23-3", Case/Package=SOT-23, Continuous Drain Current (ID)=200mA, Drain to Source Breakdown Voltage=50V, Drain to Source Resistance=3.5R, Gate to Source Voltage (Vgs)=20V, Input Capacitance=50pF, Manufacturer=Diodes, Max Operating Temperature=150°C, Max Power Dissipation=300mW, Min Operating Temperature=-55°C, Package Quantity=3000, Supplier Part Number 1=BSS138-FDICT-ND, Threshold Voltage=1.2V
Q3: "N-Channel Advanced Power MOSFET 30V/20A"
R1: library part RESISTOR, "Resistor, 0603R, 3.3K, 1%"
R2 R10 R12 R19: library part RESISTOR, "Resistor, 0603R, 100R, 1%"
R3 R9 R27: library part RESISTOR, "Resistor, 0603R, 20K, 1%"
R4: library part RESISTOR, "Resistor, 0603R, 100K, 1%"
R5: library part RESISTOR, "Resistor, 0603R, 33K, 1%"
R6: library part RESISTOR, "Resistor, 0603R, 50K, 1%"
R7: library part RESISTOR, "Resistor, 0603R, 115K, 1%"
R8: library part RESISTOR, "Resistor, 0603R, 10K, 1%"
R11: library part RESISTOR, "Resistor, 0805R, 0R, 1%"
R13 R14: library part RESISTOR, "Resistor, 0603R, NC/10K, 1%"
R15 R16: library part RESISTOR, "Resistor, 0603R, 51K, 1%"
R17 R18 R25 R26: library part RESISTOR, "Resistor, 0603R, 2R, 1%"
R20 R21 R22 R23 R24: library part RESISTOR, "Resistor, 0603R, 1K, 1%"
R28 R30: library part RESISTOR, "Resistor, 0603R, 0R, 1%"
R29: library part RESISTOR, "Resistor, 1206R, 20mR, 1%"
TP1 TP2 TP3 TP4 TP5 TP6 TP7 TP8: library part TEST_POINT, "SMD Test Point"

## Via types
v1: diameter 24, hole 12, Top Layer to Bottom Layer, 166 vias
v2: diameter 32, hole 20, Top Layer to Bottom Layer, 18 vias

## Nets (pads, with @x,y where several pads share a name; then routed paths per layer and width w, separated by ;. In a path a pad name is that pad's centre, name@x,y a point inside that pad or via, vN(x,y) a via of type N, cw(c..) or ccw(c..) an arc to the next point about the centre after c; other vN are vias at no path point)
BAT+: C16.1 C18.1 C19.1 C20.1 IC1.23 IC1.24 L1.2 R20.1 R21.1 R22.1 R23.1 R24.1 R27.2 TP7.1 | length 9672.5
  Bottom Layer w10: v1(5784.25,7408.42) 5473.65,7408.42 ccw(c11378.15,3783.6) 5322.83,7150.43 5322.83,6830.71 5267.39,6775.26 R22.1@5158.95,6775.26 5133.86,6750.17 5133.86,6433.07 5332.06,6234.87 5332.06,4970.25 5332.06,4968.33 ccw(c6465.72,5641.16) 5378.26,4895.97 ccw(c6169.88,5438.42) 5491.32,4759.84 5494.22,4759.84 5549.21,4759.84 R21.1@5647.64,4661.42 5647.64,4656.66 5647.64,4653.55 ccw(c7886.13,7130.48) 6965.84,3921.26 6966.83,3921.26 7265.75,3921.26 R24.1@7312.99,3874.02 ccw(c6416.16,8533.09) 8174.52,4126.34 8175.29,4126.65 ccw(c5185.59,8359.25) R20.1@8917.32,4763.78 8956.69,4803.15 9115.01,4803.15 ccw(c6811.15,6412.17) 9263.78,5040.55 9263.78,6719.33 R23.1@9391.23,6846.79 ; v1(5972.44,7559.06) 6001.97,7559.06 R27.2@6029.53,7586.61
BAT-: C21.2 C24.2 IC2.5 IC2.7 IC2.8 IC2.9 IC3.5 IC3.7 IC3.8 IC3.9 TP8.1 | length 205.3
  Top Layer w10: IC3.8@6244.29,7685.28 6244.29,7596.26 C24.2@6253.94,7586.61
  Bottom Layer w10: IC2.5@6244.29,7685.28 6244.29,7596.26 C21.2@6253.94,7586.61
  other v2: 6125.98,7779.53 6212.6,7779.53 6169.29,7811.02 6125.98,7842.52 6212.6,7842.52
CC1: IC1.32 J1.A5 | length 1479.6
  Top Layer w7: v1(7015.75,7401.57) 7015.75,7417.32 7023.62,7425.2 IC1.32@7059.06,7425.2
  MID2 w7: v1(7015.75,7401.57) 7015.75,7464.57 6929.13,7551.18 6838.58,7551.18 6787.4,7602.36 6787.4,8090.55 6925.2,8228.35 v1(7215.81,8228.35)
  Bottom Layer w7: v1(7215.81,8228.35) 7215.81,8227.53 7234.25,8209.08 J1.A5@7234.25,8140.79
CC2: IC1.33 J1.B5 | length 1771.1
  Top Layer w7: v1(7059.06,7358.27) 7082.68,7381.89 IC1.33@7102.36,7381.89
  MID2 w7: v1(7059.06,7358.27) 7025.79,7358.27 6950.98,7433.07 6909.45,7433.07 6771.65,7570.87 6771.65,8094.6 6932.96,8255.91 7228.35,8255.91 7244.48,8239.77 7244.48,8220.09 7263.78,8200.79 7351.62,8200.79 v1(7379.18,8228.35)
  Bottom Layer w7: J1.B5@7352.36,8140.79 7352.36,8201.53 v1(7379.18,8228.35)
COIL_V: C14.1 C15.G1 C15.G2 D1.A R3.2 TP3.1 | length 1163.6
  Top Layer w25: R3.2@7710.63,7362.2 7712.6,7364.17 7776.61,7364.17 D1.A@7778.58,7366.14
  Top Layer w30: D1.A@7778.58,7366.14 7778.58,7376.14 7783.58,7381.14 7793.58,7381.14 7879.11,7466.67 8007.89,7466.67 8047.24,7427.31 8047.24,7377.95 8074.8,7350.39 v1(8106.3,7350.39)
  Bottom Layer w30: v1(8106.3,7350.39) v2(8748.03,7350.39)
DMA1: IC1.40 J2.2 | length 986.3
  Top Layer w7: IC1.40@7212.6,7381.89 7212.6,7334.4 v1(7220.22,7326.77)
  MID2 w7: v1(7220.22,7326.77) 7220.22,7354.33 7268.04,7402.15 7445.45,7402.15 7511.81,7468.5 7511.81,7775.7 7433.18,7854.33 7378.25,7854.33 7322.83,7909.74 J2.2@7322.83,7919.59
DMC: IC1.35 J1.A7 J1.B7 | length 2142.3
  Top Layer w7: IC1.35@7133.86,7381.89 7133.86,7343.34 7149.11,7328.09 v1(7149.11,7326.77)
  MID2 w7: v1(7149.11,7326.77) 7149.11,7327.59 7126.31,7350.39 7090.55,7350.39 7072.81,7332.65 6911.44,7332.65 6751.97,7492.13 6751.97,8177.17 6850.39,8275.59 7279.53,8275.59 7308.81,8246.31 v1(7308.81,8228.35)
  Bottom Layer w7: J1.B7@7253.94,8140.79 7253.94,8214.57 7248.03,8220.47 7248.03,8240.16 7263.78,8255.91 7303.15,8255.91 7308.21,8250.85 7308.21,8228.13 7308.81,8227.53 7293.31,8212.03 J1.A7@7293.31,8140.79
DNGATE1: IC1.55 R25.2 | length 825.4
  Top Layer w7: IC1.55@7381.89,7519.69 7799.21,7519.69 7919.07,7639.54 7919.07,7726.16 7952.76,7759.84 v1(7972.44,7759.84)
  Bottom Layer w7: v1(7972.44,7759.84) R25.2@8057.09,7759.84
DNGATE2: IC1.53 R26.1 | length 1048.6
  Top Layer w7: IC1.53@7381.89,7488.19 7812.26,7488.19 7948.82,7624.75 7948.82,7709.24 7958.95,7719.37 7996.32,7719.37 8015.75,7738.8 8015.75,7854.33 v1(7972.44,7897.64)
  Bottom Layer w7: v1(7972.44,7897.64) R26.1@8057.09,7897.64
DPA1: IC1.39 J2.3 | length 1056.7
  Top Layer w7: v1(7189.22,7326.77) 7196.85,7334.4 IC1.39@7196.85,7381.89
  MID2 w7: v1(7189.22,7326.77) 7189.22,7346.7 7258.67,7416.15 7439.65,7416.15 7497.81,7474.3 7497.81,7769.91 7427.39,7840.33 7372.45,7840.33 7346.64,7866.14 7287.7,7866.14 7244.09,7909.74 J2.3@7244.09,7919.59
DPC: IC1.34 J1.A6 J1.B6 | length 2180.1
  Top Layer w7: v1(7118.11,7326.77) IC1.34@7118.11,7381.89 ; v1(7277.81,8228.35) 7278.48,8227.67 7278.48,8211.2 7284.96,8204.72 7332.65,8204.72 7339.13,8211.2 7339.13,8227.67 v1(7339.81,8228.35)
  MID2 w7: v1(7118.11,7326.77) 7090.55,7326.77 7081.43,7317.65 6905.23,7317.65 6736.97,7485.91 6736.97,8183.38 6844.18,8290.59 7296.02,8290.59 7340.13,8246.49 7340.13,8228.67 v1(7339.81,8228.35)
  Bottom Layer w7: J1.A6@7273.62,8140.79 7273.62,8219.56 7277.81,8223.75 v1(7277.81,8228.35) ; J1.B6@7312.99,8140.79 7312.99,8200.71 7339.81,8227.53 v1(7339.81,8228.35)
FOD_DET: D2.K D3.A IC1.48 R3.1 | length 453.6
  Top Layer w7: IC1.48@7338.58,7381.89 7440.94,7381.89 7460.63,7362.2 v1(7578.74,7362.2) R3.1@7643.7,7362.2
  Bottom Layer w25: v1(7578.74,7362.2) 7617.54,7362.2 7625.04,7369.7 D2.K@7625.04,7370.08 D3.A@7625.04,7460.63
GND: C2.2 C3.2 C4.1 C5.2 C6.2 C7.1 C8.2 C9.2 C11.2 C16.2 C18.2 C19.2 C20.2 C22.2 C23.2 D2.A D4.A IC1.10 IC1.43 IC1.65 IC2.1 IC2.2 IC2.3 IC2.4 IC3.1 IC3.2 IC3.3 IC3.4 J1.A1/B12 J1.B1/A12 J1.S1 J1.S2 J1.S3 J1.S4 J2.4 J2.P1 J2.P2 LED1.4 Q2.2 R5.2 R6.2 R7.2 R8.1 R9.2 R15.2 R16.2 R29.2 R30.1 TP2.1 TP6.1 | length 2250.2
  Top Layer w7: 7078.74,7685.04 IC1.65@7196.85,7566.93 ; IC1.10@7196.85,7704.72 IC1.65@7196.85,7566.93 ; IC1.43@7259.84,7381.89 7259.84,7503.94 v2(7220.47,7543.31) IC1.65@7196.85,7566.93
  Top Layer w10: Q2.2@5175.2,6515.75 v1(5224.41,6515.75) ; v1(5224.41,6653.54) 5224.41,6818.9 v1(5236.22,6830.71)
  Top Layer w40: v2(8330.71,7574.8) R29.2@8378.52,7574.8 R30.1@8378.52,7488.19
  Bottom Layer w10: v1(5224.41,6515.75) v1(5224.41,6653.54) ; v1(5236.22,6830.71) 5267.72,6862.2 5267.72,7121.37 cw(c7590.68,5924.77) 5459.69,7437.01 5892.82,7437.01 5964.57,7365.26 v1(5964.57,7342.52)
  other v1: 7283.46,4133.86 7677.17,4133.86 7677.17,4330.71 8070.87,4330.71 6102.36,4527.56 7677.17,4527.56 8070.87,4527.56 8464.57,4527.56 5196.85,5354.33 9370.08,5511.81 5157.48,5629.92 9448.82,5708.66 9448.82,5905.51 5157.48,5944.88 9370.08,6456.69 9370.08,6614.17 9291.34,7047.24 6011.81,7342.52 6397.64,7342.52 6437.01,7342.52 6476.38,7342.52 9047.24,7358.27 7913.39,7519.69 6377.95,7598.43 6456.69,7598.43 7835.82,7656.86 6377.95,7716.54 6456.69,7716.54 7874.02,7716.54 8811.02,7716.54 6456.69,7874.02 5925.2,7893.7 5964.57,7893.7 6003.94,7893.7 6043.31,7893.7 6299.21,7893.7 6338.58,7893.7 5964.57,7933.07 6003.94,7933.07 6043.31,7933.07 6299.21,7933.07 6338.58,7933.07 7874.02,7952.76 6023.62,7972.44 6299.21,7972.44 6338.58,7972.44 6062.99,7992.13 6456.69,7992.13 6574.8,7992.13 8425.2,7992.13 6102.36,8011.81 6141.73,8011.81 6181.1,8011.81 6220.47,8011.81 6259.84,8011.81 6299.21,8011.81 6338.58,8011.81 7874.02,8070.87 8070.87,8070.87 8267.72,8070.87 7952.76,8149.61 8149.61,8149.61
  other v2: 7122.05,7444.88 7220.47,7444.88 7318.9,7444.88 8377.95,7527.56 7122.05,7543.31 7318.9,7543.31 7122.05,7641.73 7220.47,7641.73 7318.9,7641.73
IGND: IC1.44 R30.2 | length 1338.8
  Top Layer w7: v1(7251.97,7326.77) 7251.97,7327.1 7275.59,7350.72 IC1.44@7275.59,7381.89
  Top Layer w30: R30.2@8378.52,7421.26 v1(8417.32,7421.26)
  MID2 w7: v1(7251.97,7326.77) 7252.95,7327.75 7252.95,7357.66 7281.55,7386.27 7874.46,7386.27 7885.83,7397.64 8027.56,7397.64 8066.93,7437.01 8401.57,7437.01 v1(8417.32,7421.26)
ISENSE: IC1.45 R28.2 | length 1200.4
  Top Layer w7: v1(7283.46,7326.77) 7283.46,7331.37 7291.34,7339.25 IC1.45@7291.34,7381.89
  Top Layer w25: v1(8314.96,7384.39) R28.2@8314.96,7421.26
  MID2 w7: v1(7283.46,7326.77) 7283.46,7354.33 7301.4,7372.27 7371.94,7372.27 7412.56,7331.65 7898.47,7331.65 7943.61,7376.79 8302.76,7376.79 8310.36,7384.39 v1(8314.96,7384.39)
